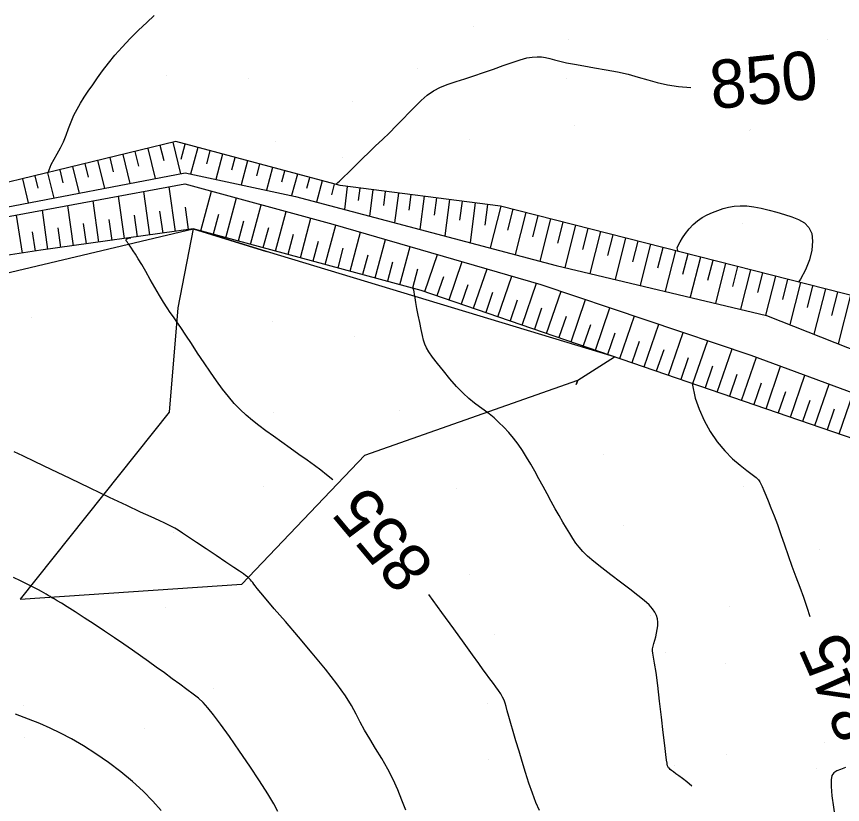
# Model space of a CAD drawing. Extents: x 400243 to 403697, y 4403637 to 4408083.
# Drawn here: x 402826.2 to 402954.4, y 4406092.2 to 4406214.4 of the extents above; entities that cross this region are included whole.
import ezdxf

# ---------------------------------------------------------------- set-up
doc = ezdxf.new("R2010")
doc.units = 0
doc.layers.add('HH_IC', color=7, linetype='Continuous')

msp = doc.modelspace()

# ---------------------------------------------------------------- linework, layer by layer
at = {"layer": 'HH_IC'}
for p, q in [((402897.11, 4406212.85), (402897.11, 4406212.85)), ((402911.86, 4406210.83), (402911.86, 4406210.83)), ((402951.99, 4406210.8), (402951.99, 4406210.8)), ((402940.18, 4406207.4), (402940.18, 4406207.4)), ((402888.5, 4406206.28), (402888.5, 4406206.28)), ((402849.53, 4406205.18), (402849.53, 4406205.18)), ((402862.2, 4406204.8), (402862.2, 4406204.8)), ((402911.54, 4406204.71), (402911.54, 4406204.71)), ((402878.35, 4406201.15), (402878.35, 4406201.15)), ((402912.86, 4406197.49), (402912.86, 4406197.49)), ((402940.08, 4406196.93), (402940.08, 4406196.93)), ((402940.01, 4406196.78), (402940.01, 4406196.78)), ((402850.92, 4406195), (402809.29, 4406184.89)), ((402849.09, 4406192.02), (402848.51, 4406194.41)), ((402850.45, 4406194.89), (402851.64, 4406190.01)), ((402850.92, 4406195), (402850.92, 4406195)), ((402876.44, 4406188.18), (402850.92, 4406195)), ((402851.76, 4406192.26), (402852.39, 4406194.61)), ((402866.33, 4406195.03), (402866.33, 4406195.03)), ((402896.51, 4406195.38), (402896.51, 4406195.38)), ((402845.18, 4406191.18), (402844.62, 4406193.47)), ((402846.56, 4406193.94), (402847.7, 4406189.26)), ((402854.32, 4406194.09), (402853.22, 4406189.97)), ((402855.71, 4406191.56), (402856.25, 4406193.57)), ((402858.18, 4406193.06), (402857.13, 4406189.13)), ((402838.79, 4406192.05), (402839.83, 4406187.76)), ((402841.27, 4406190.33), (402840.73, 4406192.53)), ((402842.68, 4406193), (402843.77, 4406188.51)), ((402859.6, 4406190.63), (402860.12, 4406192.54)), ((402862.05, 4406192.02), (402861.05, 4406188.29)), ((402876.75, 4406192.56), (402876.75, 4406192.56)), ((402833.45, 4406188.63), (402832.96, 4406190.64)), ((402834.9, 4406191.11), (402835.9, 4406187)), ((402837.36, 4406189.48), (402836.85, 4406191.58)), ((402863.49, 4406189.69), (402863.98, 4406191.51)), ((402865.91, 4406190.99), (402864.97, 4406187.46)), ((402867.38, 4406188.76), (402867.84, 4406190.47)), ((402789.65, 4406178.16), (402852.37, 4406190.15)), ((402827.13, 4406189.22), (402828.03, 4406185.5)), ((402829.54, 4406187.79), (402829.07, 4406189.7)), ((402831.02, 4406190.17), (402831.97, 4406186.25)), ((402852.37, 4406190.15), (402852.37, 4406190.15)), ((402852.37, 4406190.15), (402869.49, 4406186.49)), ((402869.78, 4406189.96), (402868.88, 4406186.62)), ((402871.27, 4406187.79), (402871.71, 4406189.44)), ((402791.71, 4406177.24), (402852.3, 4406188.43)), ((402850.87, 4406181.08), (402849.9, 4406187.98)), ((402852.12, 4406188.4), (402852.12, 4406188.4)), ((402852.3, 4406188.43), (402875.27, 4406182.2)), ((402873.64, 4406188.93), (402872.76, 4406185.63)), ((402875.13, 4406186.76), (402875.57, 4406188.41)), ((402876.44, 4406188.18), (402876.44, 4406188.18)), ((402901.3, 4406185), (402876.44, 4406188.18)), ((402877.53, 4406188.04), (402877.08, 4406184.48)), ((402846.91, 4406180.52), (402845.96, 4406187.26)), ((402854.8, 4406181.14), (402856.46, 4406187.3)), ((402879.27, 4406185.88), (402879.52, 4406187.78)), ((402881.5, 4406187.53), (402880.98, 4406183.45)), ((402883.21, 4406185.11), (402883.48, 4406187.28)), ((402885.47, 4406187.02), (402884.88, 4406182.42)), ((402887.14, 4406184.34), (402887.45, 4406186.77)), ((402838.99, 4406179.41), (402838.08, 4406185.8)), ((402842.95, 4406179.96), (402842.02, 4406186.53)), ((402858.66, 4406180.1), (402860.32, 4406186.26)), ((402869.49, 4406186.49), (402869.49, 4406186.49)), ((402869.49, 4406186.49), (402909.95, 4406175.8)), ((402889.44, 4406186.52), (402888.78, 4406181.39)), ((402891.08, 4406183.57), (402891.42, 4406186.26)), ((402893.4, 4406186.01), (402892.68, 4406180.36)), ((402895.01, 4406182.8), (402895.39, 4406185.76)), ((402897.37, 4406185.5), (402896.58, 4406179.33)), ((402831.06, 4406178.29), (402830.21, 4406184.35)), ((402835.03, 4406178.85), (402834.15, 4406185.08)), ((402848.41, 4406184.21), (402848.89, 4406180.8)), ((402852.36, 4406184.85), (402852.85, 4406181.36)), ((402862.52, 4406179.06), (402864.18, 4406185.21)), ((402866.39, 4406178.02), (402868.04, 4406184.16)), ((402898.95, 4406182.04), (402899.36, 4406185.25)), ((402901.34, 4406184.99), (402899.69, 4406178.51)), ((402901.3, 4406185), (402901.3, 4406185)), ((402958.82, 4406170.35), (402901.3, 4406185)), ((402902.45, 4406181.25), (402903.28, 4406184.5)), ((402827.11, 4406177.7), (402826.2, 4406183.61)), ((402828.15, 4406183.99), (402828.15, 4406183.99)), ((402840.51, 4406182.93), (402840.97, 4406179.68)), ((402844.46, 4406183.57), (402844.93, 4406180.24)), ((402857.56, 4406183.7), (402856.73, 4406180.62)), ((402870.25, 4406176.98), (402871.9, 4406183.12)), ((402905.22, 4406184.01), (402903.56, 4406177.49)), ((402906.32, 4406180.25), (402907.15, 4406183.51)), ((402909.09, 4406183.02), (402907.42, 4406176.47)), ((402832.61, 4406181.64), (402833.05, 4406178.57)), ((402836.56, 4406182.28), (402837.01, 4406179.13)), ((402861.42, 4406182.65), (402860.59, 4406179.58)), ((402865.28, 4406181.61), (402864.45, 4406178.54)), ((402874.11, 4406175.93), (402875.76, 4406182.06)), ((402875.27, 4406182.2), (402875.27, 4406182.2)), ((402875.27, 4406182.2), (402907.55, 4406172.85)), ((402910.19, 4406179.24), (402911.03, 4406182.52)), ((402912.97, 4406182.03), (402911.3, 4406175.48)), ((402914.08, 4406178.28), (402914.91, 4406181.54)), ((402938.84, 4406182.23), (402938.84, 4406182.23)), ((402788.65, 4406166.07), (402853.59, 4406181.46)), ((402828.63, 4406180.99), (402829.09, 4406178)), ((402853.59, 4406181.46), (402829.98, 4406178.14)), ((402853.59, 4406181.46), (402829.98, 4406178.14)), ((402853.59, 4406181.46), (402851.26, 4406169.21)), ((402853.59, 4406181.46), (402853.59, 4406181.46)), ((402889, 4406171.92), (402853.59, 4406181.46)), ((402889, 4406171.92), (402853.59, 4406181.46)), ((402853.59, 4406181.46), (402865.01, 4406177.93)), ((402865.01, 4406177.93), (402853.59, 4406181.46)), ((402869.14, 4406180.57), (402868.32, 4406177.5)), ((402877.97, 4406174.89), (402879.6, 4406180.95)), ((402916.84, 4406181.04), (402915.19, 4406174.56)), ((402917.96, 4406177.32), (402918.78, 4406180.55)), ((402829.92, 4406179.03), (402829.92, 4406179.03)), ((402873.01, 4406179.52), (402872.18, 4406176.45)), ((402881.84, 4406173.85), (402883.45, 4406179.84)), ((402920.72, 4406180.06), (402919.08, 4406173.63)), ((402921.84, 4406176.37), (402922.66, 4406179.56)), ((402924.6, 4406179.07), (402922.98, 4406172.71)), ((402829.98, 4406178.14), (402808.25, 4406174.81)), ((402829.98, 4406178.14), (402808.25, 4406174.81)), ((402829.98, 4406178.14), (402829.98, 4406178.14)), ((402918.99, 4406161.62), (402865.01, 4406177.93)), ((402876.86, 4406178.46), (402876.04, 4406175.41)), ((402885.7, 4406172.81), (402887.29, 4406178.72)), ((402925.73, 4406175.41), (402926.53, 4406178.58)), ((402928.47, 4406178.08), (402926.87, 4406171.78)), ((402880.71, 4406177.38), (402879.9, 4406174.37)), ((402889.55, 4406171.73), (402891.52, 4406177.5)), ((402893.33, 4406170.44), (402895.37, 4406176.38)), ((402929.61, 4406174.45), (402930.41, 4406177.59)), ((402932.35, 4406177.09), (402930.76, 4406170.86)), ((402933.5, 4406173.5), (402934.29, 4406176.6)), ((402884.57, 4406176.31), (402883.77, 4406173.33)), ((402888.42, 4406175.23), (402887.63, 4406172.29)), ((402897.12, 4406169.14), (402899.22, 4406175.27)), ((402909.95, 4406175.8), (402942.58, 4406168.04)), ((402936.23, 4406176.11), (402934.65, 4406169.93)), ((402937.38, 4406172.54), (402938.16, 4406175.61)), ((402940.1, 4406175.12), (402938.54, 4406169)), ((402939.61, 4406175.38), (402939.61, 4406175.38)), ((402892.44, 4406174.01), (402891.44, 4406171.09)), ((402900.9, 4406167.84), (402903.06, 4406174.15)), ((402941.26, 4406171.58), (402942.04, 4406174.63)), ((402943.98, 4406174.13), (402942.44, 4406168.08)), ((402896.26, 4406172.81), (402895.22, 4406169.79)), ((402904.68, 4406166.54), (402906.91, 4406173.04)), ((402907.55, 4406172.85), (402907.55, 4406172.85)), ((402907.55, 4406172.85), (402940.17, 4406161.87)), ((402945.12, 4406170.5), (402945.92, 4406173.64)), ((402947.85, 4406173.14), (402946.19, 4406166.61)), ((402948.93, 4406169.26), (402949.79, 4406172.65)), ((402889, 4406171.92), (402889, 4406171.92)), ((402956.35, 4406148.82), (402889, 4406171.92)), ((402956.35, 4406148.82), (402889, 4406171.92)), ((402900.07, 4406171.6), (402899.01, 4406168.49)), ((402908.47, 4406165.24), (402910.71, 4406171.79)), ((402951.73, 4406172.16), (402949.94, 4406165.13)), ((402952.74, 4406168.03), (402953.67, 4406171.66)), ((402903.89, 4406170.39), (402902.79, 4406167.19)), ((402912.25, 4406163.95), (402914.5, 4406170.51)), ((402955.61, 4406171.17), (402953.69, 4406163.65)), ((402851.26, 4406169.21), (402849.91, 4406153.03)), ((402851.26, 4406169.21), (402851.26, 4406169.21)), ((402907.69, 4406169.16), (402906.57, 4406165.89)), ((402916.03, 4406162.65), (402918.29, 4406169.24)), ((402828.52, 4406167.77), (402828.52, 4406167.77)), ((402911.48, 4406167.87), (402910.36, 4406164.6)), ((402919.82, 4406161.35), (402922.08, 4406167.96)), ((402942.19, 4406167.72), (402942.19, 4406167.72)), ((402942.58, 4406168.04), (402977.07, 4406154.39)), ((402865.87, 4406167.1), (402865.87, 4406167.1)), ((402915.27, 4406166.59), (402914.14, 4406163.3)), ((402923.6, 4406160.05), (402925.87, 4406166.68)), ((402878.64, 4406164.83), (402878.64, 4406164.83)), ((402919.06, 4406165.3), (402917.92, 4406162)), ((402927.38, 4406158.75), (402929.67, 4406165.41)), ((402922.84, 4406164.01), (402921.71, 4406160.7)), ((402931.17, 4406157.46), (402933.46, 4406164.13)), ((402926.63, 4406162.72), (402925.49, 4406159.4)), ((402934.95, 4406156.16), (402937.25, 4406162.85)), ((402913.33, 4406157.98), (402918.99, 4406161.62)), ((402918.99, 4406161.62), (402918.99, 4406161.62)), ((402930.42, 4406161.44), (402929.27, 4406158.1)), ((402938.73, 4406154.86), (402941.03, 4406161.55)), ((402940.17, 4406161.87), (402940.17, 4406161.87)), ((402940.17, 4406161.87), (402960.88, 4406154.21)), ((402934.2, 4406160.15), (402933.06, 4406156.81)), ((402942.52, 4406153.56), (402944.78, 4406160.16)), ((402937.99, 4406158.86), (402936.84, 4406155.51)), ((402946.3, 4406152.26), (402948.53, 4406158.77)), ((402880.28, 4406146.35), (402913.33, 4406157.98)), ((402913.06, 4406157.32), (402913.33, 4406157.98)), ((402913.33, 4406157.98), (402913.06, 4406157.32)), ((402913.33, 4406157.98), (402913.33, 4406157.98)), ((402941.77, 4406157.53), (402940.63, 4406154.21)), ((402950.08, 4406150.97), (402952.29, 4406157.39)), ((402945.53, 4406156.19), (402944.41, 4406152.91)), ((402953.87, 4406149.67), (402956.04, 4406156)), ((402949.3, 4406154.85), (402948.19, 4406151.61)), ((402885.71, 4406153.33), (402885.71, 4406153.33)), ((402953.07, 4406153.5), (402951.98, 4406150.32)), ((402849.91, 4406153.03), (402826.75, 4406124.04)), ((402849.91, 4406153.03), (402849.91, 4406153.03)), ((402866.08, 4406153.04), (402866.08, 4406153.04)), ((402861.16, 4406126.37), (402880.28, 4406146.35)), ((402880.28, 4406146.35), (402880.28, 4406146.35)), ((402917.23, 4406146.52), (402917.23, 4406146.52)), ((402864.52, 4406141.57), (402864.52, 4406141.57)), ((402894.55, 4406141.23), (402894.55, 4406141.23)), ((402938.96, 4406141.55), (402938.96, 4406141.55)), ((402920.36, 4406135.49), (402920.36, 4406135.49)), ((402850.56, 4406134.32), (402850.56, 4406134.32)), ((402950.74, 4406131.74), (402950.74, 4406131.74)), ((402896.47, 4406127.88), (402896.47, 4406127.88)), ((402826.75, 4406124.04), (402861.16, 4406126.37)), ((402861.16, 4406126.37), (402861.16, 4406126.37)), ((402826.75, 4406124.04), (402826.75, 4406124.04)), ((402849.36, 4406122.8), (402849.36, 4406122.8)), ((402936.9, 4406122.94), (402936.9, 4406122.94)), ((402924.54, 4406121.47), (402924.54, 4406121.47)), ((402900.42, 4406118.55), (402900.42, 4406118.55)), ((402926.9, 4406115.78), (402926.9, 4406115.78)), ((402936.16, 4406114.12), (402936.16, 4406114.12)), ((402948.96, 4406114.19), (402948.96, 4406114.19)), ((402856.71, 4406110.23), (402856.71, 4406110.23)), ((402827.34, 4406107.58), (402827.34, 4406107.58)), ((402899.22, 4406107.86), (402899.22, 4406107.86)), ((402846.06, 4406104.03), (402846.06, 4406104.03)), ((402827.49, 4406102.65), (402827.49, 4406102.65)), ((402951.52, 4406101.87), (402951.52, 4406101.87)), ((402936.32, 4406099.96), (402936.32, 4406099.96)), ((402899.45, 4406099.15), (402899.45, 4406099.15)), ((402928.36, 4406098.21), (402928.36, 4406098.21)), ((402950.39, 4406097.73), (402950.39, 4406097.73))]:
    msp.add_line(p, q, dxfattribs=at)
for points in [[(402831.1, 4406190.19), (402831.57, 4406191.47), (402832.02, 4406192.27), (402832.53, 4406193.11), (402833.02, 4406194.01), (402833.48, 4406194.98), (402833.89, 4406196), (402834.28, 4406197.04), (402834.68, 4406198.08), (402835.12, 4406199.08), (402835.59, 4406200.04), (402836.12, 4406200.97), (402836.71, 4406201.89), (402837.34, 4406202.83), (402838.03, 4406203.82), (402838.77, 4406204.87), (402839.57, 4406205.99), (402840.47, 4406207.16), (402841.47, 4406208.39), (402842.59, 4406209.67), (402843.83, 4406210.98), (402845.12, 4406212.27), (402846.4, 4406213.48), (402847.57, 4406214.55)], [(402875.88, 4406188.43), (402875.95, 4406188.53), (402876.09, 4406188.67), (402876.3, 4406188.88), (402876.62, 4406189.17), (402877.05, 4406189.58), (402877.6, 4406190.12), (402878.28, 4406190.78), (402879.06, 4406191.55), (402879.93, 4406192.41), (402880.89, 4406193.33), (402881.91, 4406194.32), (402882.98, 4406195.34), (402884.06, 4406196.38), (402885.13, 4406197.43), (402886.15, 4406198.48), (402887.12, 4406199.5), (402888.05, 4406200.47), (402888.98, 4406201.37), (402889.93, 4406202.18), (402890.93, 4406202.87), (402892.01, 4406203.44), (402893.18, 4406203.91), (402894.43, 4406204.33), (402895.77, 4406204.74), (402897.19, 4406205.19), (402898.69, 4406205.71), (402900.22, 4406206.26), (402901.71, 4406206.8), (402903.1, 4406207.29), (402904.34, 4406207.69), (402905.38, 4406207.97), (402906.24, 4406208.12), (402906.99, 4406208.17), (402907.66, 4406208.14), (402908.3, 4406208.04), (402908.96, 4406207.89), (402909.69, 4406207.7), (402910.53, 4406207.48), (402911.54, 4406207.24), (402912.78, 4406206.99), (402914.26, 4406206.73), (402915.92, 4406206.45), (402917.68, 4406206.15), (402919.44, 4406205.82), (402921.14, 4406205.44), (402922.69, 4406205.01), (402924.17, 4406204.57), (402925.64, 4406204.15), (402927.2, 4406203.79), (402928.92, 4406203.54), (402930.85, 4406203.41)], [(402931.2, 4406182.15), (402931.88, 4406182.73), (402932.62, 4406183.23), (402933.4, 4406183.65), (402934.21, 4406184.01), (402935.02, 4406184.33), (402935.85, 4406184.6), (402936.69, 4406184.82), (402937.56, 4406184.98), (402938.5, 4406185.06), (402939.51, 4406185.03), (402940.61, 4406184.9), (402941.77, 4406184.67), (402942.98, 4406184.38), (402944.19, 4406184.05), (402945.38, 4406183.69), (402946.53, 4406183.33), (402947.57, 4406182.91), (402948.46, 4406182.38), (402949.16, 4406181.67), (402949.6, 4406180.74), (402949.75, 4406179.55), (402949.62, 4406178.16), (402949.25, 4406176.66), (402948.66, 4406175.13), (402947.87, 4406173.66), (402947.6, 4406173.29)], [(402928.81, 4406178.1), (402928.7, 4406178.54), (402928.88, 4406178.91), (402929.17, 4406179.43), (402929.56, 4406180.06), (402930.03, 4406180.77), (402930.58, 4406181.48), (402931.2, 4406182.15)], [(402875.28, 4406142.52), (402874.32, 4406143.34), (402873.41, 4406144.04), (402872.42, 4406144.75), (402871.28, 4406145.57), (402870.02, 4406146.48), (402868.69, 4406147.43), (402867.36, 4406148.39), (402866.08, 4406149.31), (402864.9, 4406150.16), (402863.82, 4406150.96), (402862.8, 4406151.75), (402861.84, 4406152.56), (402860.91, 4406153.43), (402860, 4406154.39), (402859.09, 4406155.45), (402858.17, 4406156.61), (402857.24, 4406157.87), (402856.28, 4406159.24), (402855.3, 4406160.7), (402854.31, 4406162.2), (402853.36, 4406163.66), (402852.48, 4406165), (402851.71, 4406166.15), (402851.08, 4406167.07), (402850.55, 4406167.82), (402850.06, 4406168.5), (402849.57, 4406169.23), (402849.02, 4406170.09), (402848.38, 4406171.15), (402847.68, 4406172.36), (402846.96, 4406173.62), (402846.26, 4406174.85), (402845.63, 4406175.94), (402845.09, 4406176.84), (402844.66, 4406177.54), (402844.31, 4406178.08), (402844.04, 4406178.48), (402843.84, 4406178.78), (402843.69, 4406178.99), (402843.58, 4406179.15), (402843.5, 4406179.26), (402843.43, 4406179.35), (402843.37, 4406179.43), (402843.3, 4406179.52), (402843.24, 4406179.6), (402843.2, 4406179.69), (402843.2, 4406179.78), (402843.26, 4406179.86), (402843.39, 4406179.93), (402843.57, 4406180), (402843.79, 4406180.06), (402843.95, 4406180.1)], [(402931.01, 4406095.04), (402930.24, 4406095.68), (402929.55, 4406096.2), (402928.97, 4406096.62), (402928.5, 4406096.96), (402928.13, 4406097.23), (402927.86, 4406097.44), (402927.66, 4406097.61), (402927.51, 4406097.75), (402927.4, 4406097.87), (402927.33, 4406097.98), (402927.28, 4406098.08), (402927.24, 4406098.16), (402927.22, 4406098.24), (402927.19, 4406098.35), (402927.15, 4406098.58), (402927.08, 4406099.07), (402926.97, 4406099.95), (402926.81, 4406101.35), (402926.57, 4406103.34), (402926.3, 4406105.72), (402926, 4406108.23), (402925.71, 4406110.63), (402925.44, 4406112.64), (402925.22, 4406114.08), (402925.06, 4406115.03), (402924.95, 4406115.63), (402924.91, 4406116.02), (402924.92, 4406116.35), (402924.99, 4406116.73), (402925.11, 4406117.18), (402925.25, 4406117.68), (402925.4, 4406118.21), (402925.54, 4406118.77), (402925.64, 4406119.33), (402925.7, 4406119.9), (402925.71, 4406120.45), (402925.65, 4406121), (402925.51, 4406121.52), (402925.27, 4406122.03), (402924.9, 4406122.55), (402924.36, 4406123.13), (402923.61, 4406123.81), (402922.62, 4406124.62), (402921.36, 4406125.59), (402919.94, 4406126.67), (402918.45, 4406127.79), (402917.04, 4406128.88), (402915.8, 4406129.87), (402914.82, 4406130.71), (402914.08, 4406131.43), (402913.49, 4406132.09), (402913, 4406132.74), (402912.54, 4406133.43), (402912.05, 4406134.2), (402911.53, 4406135.06), (402910.97, 4406135.99), (402910.39, 4406136.99), (402909.79, 4406138.06), (402909.17, 4406139.19), (402908.55, 4406140.35), (402907.91, 4406141.53), (402907.27, 4406142.71), (402906.63, 4406143.87), (402905.99, 4406144.98), (402905.35, 4406146.05), (402904.7, 4406147.08), (402904.03, 4406148.06), (402903.33, 4406148.99), (402902.6, 4406149.87), (402901.84, 4406150.69), (402901.07, 4406151.45), (402900.3, 4406152.15), (402899.54, 4406152.77), (402898.79, 4406153.33), (402898.03, 4406153.87), (402897.25, 4406154.45), (402896.41, 4406155.13), (402895.49, 4406155.98), (402894.49, 4406157.03), (402893.45, 4406158.21), (402892.44, 4406159.43), (402891.53, 4406160.58), (402890.77, 4406161.58), (402890.21, 4406162.37), (402889.83, 4406163), (402889.57, 4406163.57), (402889.37, 4406164.18), (402889.19, 4406164.93), (402888.99, 4406165.87), (402888.77, 4406166.94), (402888.54, 4406168.06), (402888.34, 4406169.13), (402888.17, 4406170.06), (402888.04, 4406170.77), (402887.96, 4406171.3), (402887.9, 4406171.68), (402887.84, 4406171.97), (402887.77, 4406172.2), (402887.75, 4406172.26)], [(402931.07, 4406157.48), (402931.54, 4406155.2), (402932.13, 4406153.51), (402932.9, 4406151.76), (402933.84, 4406150.03), (402934.92, 4406148.42), (402936.1, 4406147.02), (402937.32, 4406145.81), (402938.49, 4406144.81), (402939.54, 4406144), (402940.38, 4406143.37), (402940.96, 4406142.91), (402941.33, 4406142.56), (402941.56, 4406142.25), (402941.73, 4406141.91), (402941.9, 4406141.48), (402942.15, 4406140.9), (402942.47, 4406140.16), (402942.85, 4406139.26), (402943.28, 4406138.2), (402943.76, 4406136.97), (402944.27, 4406135.59), (402944.81, 4406134.07), (402945.37, 4406132.47), (402945.95, 4406130.81), (402946.54, 4406129.14), (402947.15, 4406127.5), (402947.75, 4406125.88), (402948.32, 4406124.32), (402948.86, 4406122.8), (402949.33, 4406121.35)], [(402886.63, 4406091.3), (402886.02, 4406092.85), (402885.38, 4406094.44), (402884.65, 4406096.05), (402883.8, 4406097.68), (402882.88, 4406099.3), (402881.93, 4406100.86), (402881.02, 4406102.35), (402880.22, 4406103.72), (402879.55, 4406104.97), (402878.92, 4406106.2), (402878.19, 4406107.52), (402877.23, 4406109.05), (402875.91, 4406110.91), (402874.15, 4406113.16), (402872.1, 4406115.66), (402869.95, 4406118.19), (402867.92, 4406120.56), (402866.2, 4406122.55), (402864.95, 4406124.02), (402864.1, 4406125.03), (402863.57, 4406125.68), (402863.25, 4406126.09), (402863.04, 4406126.36), (402862.86, 4406126.6), (402862.68, 4406126.82), (402862.51, 4406127.02), (402862.35, 4406127.19), (402862.2, 4406127.35), (402862.04, 4406127.49), (402861.81, 4406127.67), (402861.43, 4406127.94), (402860.82, 4406128.35), (402859.91, 4406128.96), (402858.66, 4406129.79), (402857.17, 4406130.78), (402855.61, 4406131.83), (402854.13, 4406132.82), (402852.87, 4406133.66), (402851.94, 4406134.28), (402851.29, 4406134.71), (402850.79, 4406135.02), (402850.35, 4406135.26), (402849.86, 4406135.5), (402849.21, 4406135.81), (402848.32, 4406136.21), (402847.09, 4406136.78), (402845.45, 4406137.54), (402843.3, 4406138.55), (402840.62, 4406139.82), (402837.61, 4406141.25), (402834.51, 4406142.73), (402831.58, 4406144.14), (402829.07, 4406145.34), (402827.18, 4406146.25), (402825.82, 4406146.89)], [(402866.77, 4406091.11), (402866.13, 4406092.29), (402865.2, 4406093.86), (402863.93, 4406095.85), (402862.43, 4406098.12), (402860.82, 4406100.48), (402859.26, 4406102.71), (402857.88, 4406104.64), (402856.78, 4406106.1), (402855.9, 4406107.17), (402855.15, 4406107.98), (402854.42, 4406108.65), (402853.61, 4406109.3), (402852.65, 4406110.03), (402851.56, 4406110.84), (402850.37, 4406111.7), (402849.14, 4406112.6), (402847.89, 4406113.49), (402846.67, 4406114.37), (402845.45, 4406115.24), (402844.2, 4406116.13), (402842.87, 4406117.06), (402841.43, 4406118.04), (402839.88, 4406119.08), (402838.27, 4406120.13), (402836.71, 4406121.15), (402835.28, 4406122.06), (402834.07, 4406122.82), (402833.16, 4406123.39), (402832.51, 4406123.79), (402832.04, 4406124.06), (402831.69, 4406124.26), (402831.4, 4406124.43), (402831.11, 4406124.6), (402830.8, 4406124.8), (402830.45, 4406125.01), (402830.06, 4406125.24), (402829.62, 4406125.48), (402829.1, 4406125.75), (402828.49, 4406126.06), (402827.75, 4406126.42), (402826.84, 4406126.86), (402825.73, 4406127.38)], [(402907.34, 4406091.27), (402906.79, 4406092.5), (402906.25, 4406093.93), (402905.72, 4406095.5), (402905.2, 4406097.16), (402904.69, 4406098.83), (402904.19, 4406100.48), (402903.71, 4406102.04), (402903.27, 4406103.49), (402902.89, 4406104.77), (402902.58, 4406105.85), (402902.35, 4406106.71), (402902.18, 4406107.38), (402902.03, 4406107.92), (402901.86, 4406108.39), (402901.64, 4406108.85), (402901.34, 4406109.35), (402900.99, 4406109.88), (402900.6, 4406110.41), (402900.21, 4406110.93), (402899.84, 4406111.41), (402899.5, 4406111.87), (402899.12, 4406112.38), (402898.63, 4406113.07), (402897.94, 4406114.03), (402896.98, 4406115.39), (402895.67, 4406117.21), (402894.07, 4406119.44), (402892.22, 4406121.98), (402890.17, 4406124.73)], [(402848.67, 4406091.27), (402847.34, 4406092.72), (402845.85, 4406094.23), (402844.2, 4406095.75), (402842.38, 4406097.25), (402840.46, 4406098.69), (402838.5, 4406100.05), (402836.57, 4406101.28), (402834.74, 4406102.35), (402833.05, 4406103.26), (402831.44, 4406104.04), (402829.8, 4406104.74), (402828.04, 4406105.44), (402826.06, 4406106.18)], [(402954.84, 4406097.91), (402954.09, 4406097.63), (402953.49, 4406097.39), (402953.04, 4406097.11), (402952.75, 4406096.67), (402952.61, 4406095.99), (402952.6, 4406094.95), (402952.73, 4406093.51), (402952.96, 4406091.78), (402953.26, 4406089.93), (402953.6, 4406088.15), (402953.96, 4406086.58), (402954.32, 4406085.37), (402954.76, 4406084.42)]]:
    msp.add_lwpolyline(points, dxfattribs=at)

# ---------------------------------------------------------------- texts
for s, rotation, p in [('850', 6.0295, (402934.2, 4406199.99)), ('855', 129.9288, (402891.32, 4406129.2)), ('845', 113.7908, (402961.01, 4406104.16))]:
    msp.add_text(s, height=7.5, rotation=rotation, dxfattribs=at).set_placement(p)

doc.saveas('drawing.dxf')
